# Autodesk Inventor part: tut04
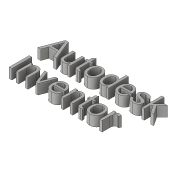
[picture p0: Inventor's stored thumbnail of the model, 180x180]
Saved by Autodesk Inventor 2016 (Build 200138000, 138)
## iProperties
Created: 2015-03
Part Number: tut04
Material: Generic
Document SubType Name: Modeling
Designer: Sandeep
Density: 1 g/cm^3
Appearance: Default
Author: Sandeep
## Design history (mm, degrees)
sketch "Sketch1"
  geometry: L1 (-22.661, 12.194)-(70.475, 12.194); L2 (70.475, 12.194)-(70.475, -0.755); L3 (70.475, -0.755)-(-22.661, -0.755); L4 (-22.661, -0.755)-(-22.661, 12.194); 1 further point
  constraints: 2 other
extrude "Extrusion1" new body sketch "Sketch1" distance "d0" = 2.5; taper "d1" = 0 deg
body "Solid1"
